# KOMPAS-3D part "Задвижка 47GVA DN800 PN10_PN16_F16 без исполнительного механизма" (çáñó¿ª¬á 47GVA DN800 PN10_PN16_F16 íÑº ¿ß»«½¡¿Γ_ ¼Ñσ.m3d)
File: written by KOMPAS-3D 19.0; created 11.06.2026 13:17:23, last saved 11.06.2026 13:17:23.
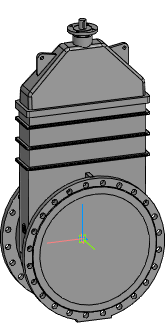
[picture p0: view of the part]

Document properties: Автор: Евгений; Полное имя файла: Z:\3.Личные\kachalov\001_3d для проектировщиков\2.2 Тип 47GVA, 47GVA.Z\_stp\_stp_Задвижка 47GVA DN40-DN1000 без исп.мех\Задвижка 47GVA DN800 PN10_PN16_F16 без исполнит_ мех.m3d

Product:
- Part/product: Задвижка 47GVA DN800 PN10_PN16_F16 без исполнительного механизма

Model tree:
1. Операция без истории:1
